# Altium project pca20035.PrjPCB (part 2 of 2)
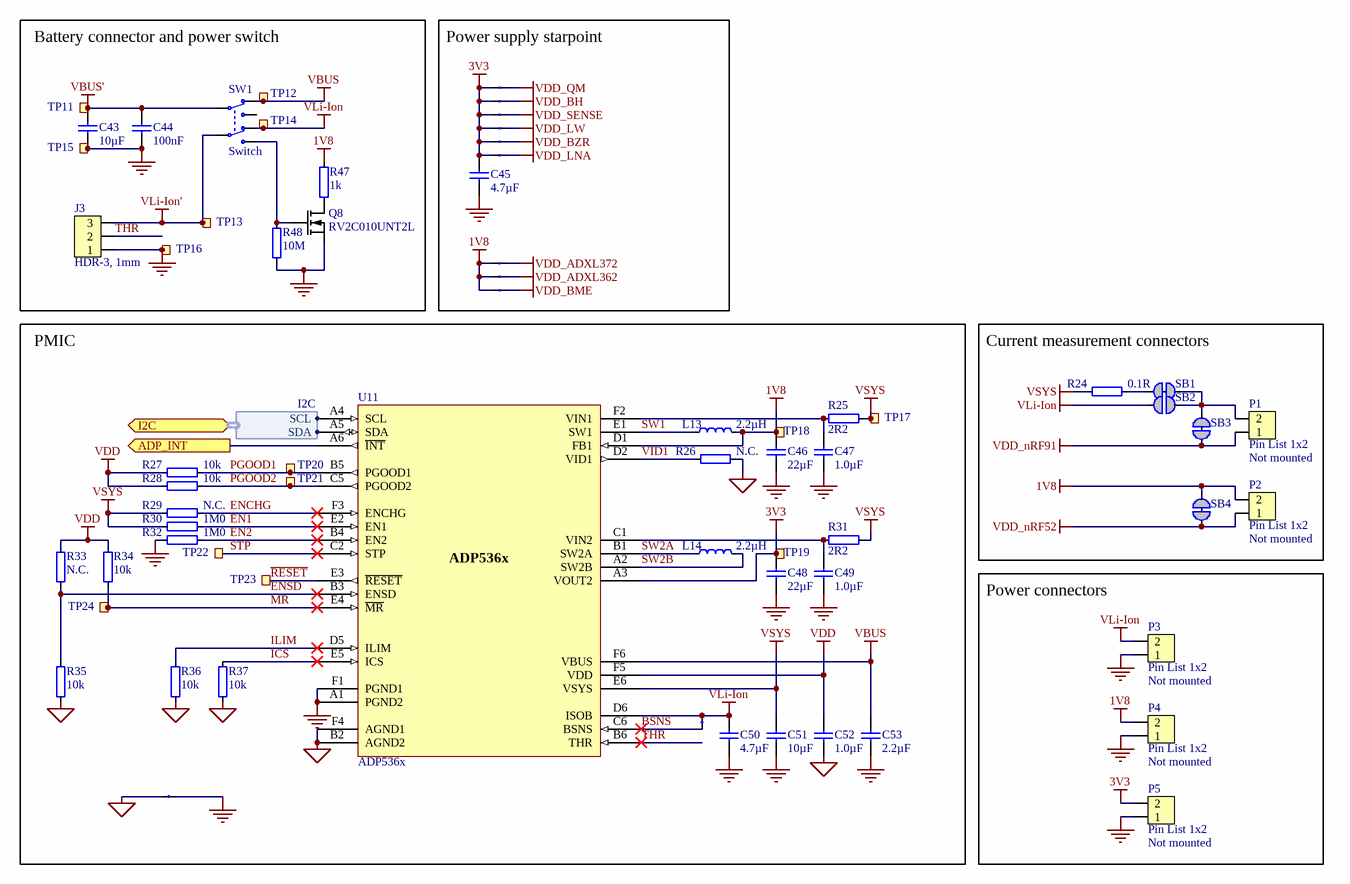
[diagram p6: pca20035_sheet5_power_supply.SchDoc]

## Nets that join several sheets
1V8: pca20035_sheet2_nrf91_mcu (C4.1 C8.2 U1.12 U5.5), pca20035_sheet4_sensors_and_leds (R22.1 R23.1), pca20035_sheet6_interface (5 pins), pca20035_sheet5_power_supply (11 pins)
GND: pca20035_sheet2_nrf91_mcu (75 pins), pca20035_sheet4_sensors_and_leds (33 pins), pca20035_sheet3_nrf52_mcu (50 pins), pca20035_sheet6_interface (20 pins), pca20035_sheet5_power_supply (22 pins)
VBUS: pca20035_sheet3_nrf52_mcu (C33.1 U6.J9), pca20035_sheet5_power_supply (C53.2 SW1.3 TP12.1 U11.F6)
VBUS': pca20035_sheet6_interface (J6.1), pca20035_sheet5_power_supply (C43.1 C44.1 SW1.2 TP11.1)
VDD_ADXL362: pca20035_sheet4_sensors_and_leds (C38.2 C39.2 U8.1 U8.14), pca20035_sheet5_power_supply (ST8.2)
VDD_ADXL372: pca20035_sheet4_sensors_and_leds (C36.2 C37.2 U7.1 U7.14), pca20035_sheet5_power_supply (ST7.2)
VDD_BH: pca20035_sheet4_sensors_and_leds (C42.2 U10.2), pca20035_sheet5_power_supply (ST2.2)
VDD_BME: pca20035_sheet4_sensors_and_leds (5 pins), pca20035_sheet5_power_supply (ST9.2)
VDD_BZR: pca20035_sheet4_sensors_and_leds (Bz1.1 D2.1), pca20035_sheet5_power_supply (ST5.2)
VDD_LNA: pca20035_sheet2_nrf91_mcu (5 pins), pca20035_sheet5_power_supply (ST6.2)
VDD_LW: pca20035_sheet4_sensors_and_leds (6 pins), pca20035_sheet5_power_supply (ST4.2)
VDD_nRF52: pca20035_sheet3_nrf52_mcu (11 pins), pca20035_sheet5_power_supply (P2.1 SB4.1)
VDD_nRF91: pca20035_sheet2_nrf91_mcu (5 pins), pca20035_sheet5_power_supply (P1.1 SB3.1)
VDD_QM: pca20035_sheet2_nrf91_mcu (C16.2 C17.2 U2.4 U3.4), pca20035_sheet5_power_supply (ST1.2)
VDD_SENSE: pca20035_sheet4_sensors_and_leds (LD1.4), pca20035_sheet5_power_supply (ST3.2)
D_N: pca20035_sheet3_nrf52_mcu (U6.J8), pca20035_sheet6_interface (J6.2 TP30.1)
D_P: pca20035_sheet3_nrf52_mcu (U6.K8), pca20035_sheet6_interface (J6.3 TP31.1)
NetSB5_2: pca20035_sheet2_nrf91_mcu (SB5.2), pca20035_sheet4_sensors_and_leds (U7.9)
NetSB6_2: pca20035_sheet2_nrf91_mcu (SB6.2), pca20035_sheet4_sensors_and_leds (U8.9)
nRF52_P0.03: pca20035_sheet3_nrf52_mcu (U6.A5), pca20035_sheet6_interface (TP25.1)
nRF52_P0.05: pca20035_sheet3_nrf52_mcu (U6.D10), pca20035_sheet6_interface (P6.2)
nRF52_P0.06: pca20035_sheet3_nrf52_mcu (U6.E9), pca20035_sheet6_interface (P6.1)
nRF52_P0.09: pca20035_sheet3_nrf52_mcu (U6.F1), pca20035_sheet6_interface (C57.2 J5.4)
nRF52_P0.10: pca20035_sheet3_nrf52_mcu (U6.E2), pca20035_sheet6_interface (C56.1 J5.2)
nRF52_P0.11: pca20035_sheet2_nrf91_mcu (U1.29), pca20035_sheet3_nrf52_mcu (U6.H8)
nRF52_P0.14: pca20035_sheet3_nrf52_mcu (U6.J7), pca20035_sheet6_interface (U12.8)
nRF52_P0.15: pca20035_sheet2_nrf91_mcu (U1.30), pca20035_sheet3_nrf52_mcu (U6.K7)
nRF52_P0.17: pca20035_sheet3_nrf52_mcu (U6.J6), pca20035_sheet6_interface (R40.1 U12.10)
nRF52_P0.19: pca20035_sheet2_nrf91_mcu (SB10.1), pca20035_sheet3_nrf52_mcu (U6.K4)
nRF52_P0.20: pca20035_sheet2_nrf91_mcu (U1.35), pca20035_sheet3_nrf52_mcu (U6.J5)
nRF52_P0.21: pca20035_sheet2_nrf91_mcu (SB7.1), pca20035_sheet3_nrf52_mcu (U6.J4)
nRF52_P0.22: pca20035_sheet2_nrf91_mcu (SB11.1), pca20035_sheet3_nrf52_mcu (U6.K3)
nRF52_P0.25: pca20035_sheet2_nrf91_mcu (SB9.1), pca20035_sheet3_nrf52_mcu (U6.K2)
nRF52_P0.26: pca20035_sheet3_nrf52_mcu (U6.C9), pca20035_sheet6_interface (P6.3)
nRF52_P0.27: pca20035_sheet3_nrf52_mcu (U6.D9), pca20035_sheet6_interface (P6.4)
nRF52_P0.28: pca20035_sheet3_nrf52_mcu (U6.A6), pca20035_sheet6_interface (P6.5)
nRF52_P0.30: pca20035_sheet3_nrf52_mcu (U6.A7), pca20035_sheet6_interface (P6.6)
nRF52_P1.00: pca20035_sheet2_nrf91_mcu (SB8.1), pca20035_sheet3_nrf52_mcu (U6.J3)
nRF52_P1.01: pca20035_sheet2_nrf91_mcu (U1.91), pca20035_sheet3_nrf52_mcu (U6.J1)
nRF52_P1.04: pca20035_sheet2_nrf91_mcu (U1.92), pca20035_sheet3_nrf52_mcu (U6.H1)
nRF52_P1.05: pca20035_sheet3_nrf52_mcu (U6.G2), pca20035_sheet6_interface (U12.12)
nRF52_P1.07: pca20035_sheet2_nrf91_mcu (U1.93), pca20035_sheet3_nrf52_mcu (U6.G1)
nRF52_P1.08: pca20035_sheet2_nrf91_mcu (U1.19), pca20035_sheet4_sensors_and_leds (R23.2 TP10.1 U9.3 U10.6), pca20035_sheet3_nrf52_mcu (U6.G9), pca20035_sheet5_power_supply (U11.A5)
nRF52_P1.09: pca20035_sheet2_nrf91_mcu (U1.20), pca20035_sheet4_sensors_and_leds (R22.2 TP9.1 U9.4 U10.5), pca20035_sheet3_nrf52_mcu (U6.F10), pca20035_sheet5_power_supply (U11.A4)
nRF52_P1.11: pca20035_sheet3_nrf52_mcu (U6.A3), pca20035_sheet6_interface (TP26.1)
nRF52_P1.13: pca20035_sheet3_nrf52_mcu (U6.A4), pca20035_sheet6_interface (SW4.2)
nRF52_SWDCLK: pca20035_sheet3_nrf52_mcu (U6.H2), pca20035_sheet6_interface (U12.3)
nRF52_SWDIO: pca20035_sheet3_nrf52_mcu (U6.J2), pca20035_sheet6_interface (U12.15)
nRF91_SWDCLK: pca20035_sheet2_nrf91_mcu (U1.33), pca20035_sheet6_interface (U12.5 U12.11)
nRF91_SWDIO: pca20035_sheet2_nrf91_mcu (U1.34), pca20035_sheet6_interface (U12.1 U12.7)
P0.00: pca20035_sheet2_nrf91_mcu (U1.95), pca20035_sheet4_sensors_and_leds (Q3.2 R44.2)
P0.01: pca20035_sheet2_nrf91_mcu (U1.96), pca20035_sheet4_sensors_and_leds (Q4.2 R45.2)
P0.02: pca20035_sheet2_nrf91_mcu (U1.97), pca20035_sheet4_sensors_and_leds (Q4.5 R46.2)
P0.03: pca20035_sheet2_nrf91_mcu (TP34.1 U1.99), pca20035_sheet4_sensors_and_leds (U7.4 U8.4)
P0.04: pca20035_sheet2_nrf91_mcu (TP35.1 U1.100), pca20035_sheet4_sensors_and_leds (U7.6 U8.6)
P0.05: pca20035_sheet2_nrf91_mcu (TP36.1 U1.2), pca20035_sheet4_sensors_and_leds (U7.7 U8.7)
P0.06: pca20035_sheet2_nrf91_mcu (U1.3), pca20035_sheet4_sensors_and_leds (U7.11)
P0.07: pca20035_sheet2_nrf91_mcu (TP37.1 U1.4), pca20035_sheet4_sensors_and_leds (U7.8)
P0.08: pca20035_sheet2_nrf91_mcu (TP38.1 U1.15), pca20035_sheet4_sensors_and_leds (U8.8)
P0.09: pca20035_sheet2_nrf91_mcu (U1.16), pca20035_sheet4_sensors_and_leds (U8.11)
P0.13/AIN0: pca20035_sheet2_nrf91_mcu (TP32.1 U1.23), pca20035_sheet6_interface (Q6.2)
P0.14/AIN1: pca20035_sheet2_nrf91_mcu (U1.24), pca20035_sheet6_interface (Q6.5)
P0.15/AIN2: pca20035_sheet2_nrf91_mcu (U1.25), pca20035_sheet6_interface (Q7.2)
P0.16/AIN3: pca20035_sheet2_nrf91_mcu (TP33.1 U1.26), pca20035_sheet6_interface (Q7.5)
P0.17/AIN4: pca20035_sheet2_nrf91_mcu (U1.28), pca20035_sheet5_power_supply (U11.A6)
P0.26: pca20035_sheet2_nrf91_mcu (U1.83), pca20035_sheet6_interface (SW3.2)
P0.27: pca20035_sheet2_nrf91_mcu (U1.84), pca20035_sheet4_sensors_and_leds (U10.7)
P0.28: pca20035_sheet2_nrf91_mcu (U1.86), pca20035_sheet4_sensors_and_leds (R21.2)
P0.29: pca20035_sheet2_nrf91_mcu (U1.87), pca20035_sheet4_sensors_and_leds (Q2.5 R41.2)
P0.30: pca20035_sheet2_nrf91_mcu (U1.88), pca20035_sheet4_sensors_and_leds (Q2.2 R42.2)
P0.31: pca20035_sheet2_nrf91_mcu (U1.89), pca20035_sheet4_sensors_and_leds (Q3.5 R43.2)
SIM_1V8: pca20035_sheet2_nrf91_mcu (U1.49), pca20035_sheet6_interface (C54.1 D3.A4 J4.C1)
SIM_CLK: pca20035_sheet2_nrf91_mcu (U1.46), pca20035_sheet6_interface (D3.A2)
SIM_DET: pca20035_sheet2_nrf91_mcu (U1.45), pca20035_sheet6_interface (R38.2)
SIM_IO: pca20035_sheet2_nrf91_mcu (U1.48), pca20035_sheet6_interface (D3.A3)
SIM_RST: pca20035_sheet2_nrf91_mcu (U1.43), pca20035_sheet6_interface (D3.A1)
